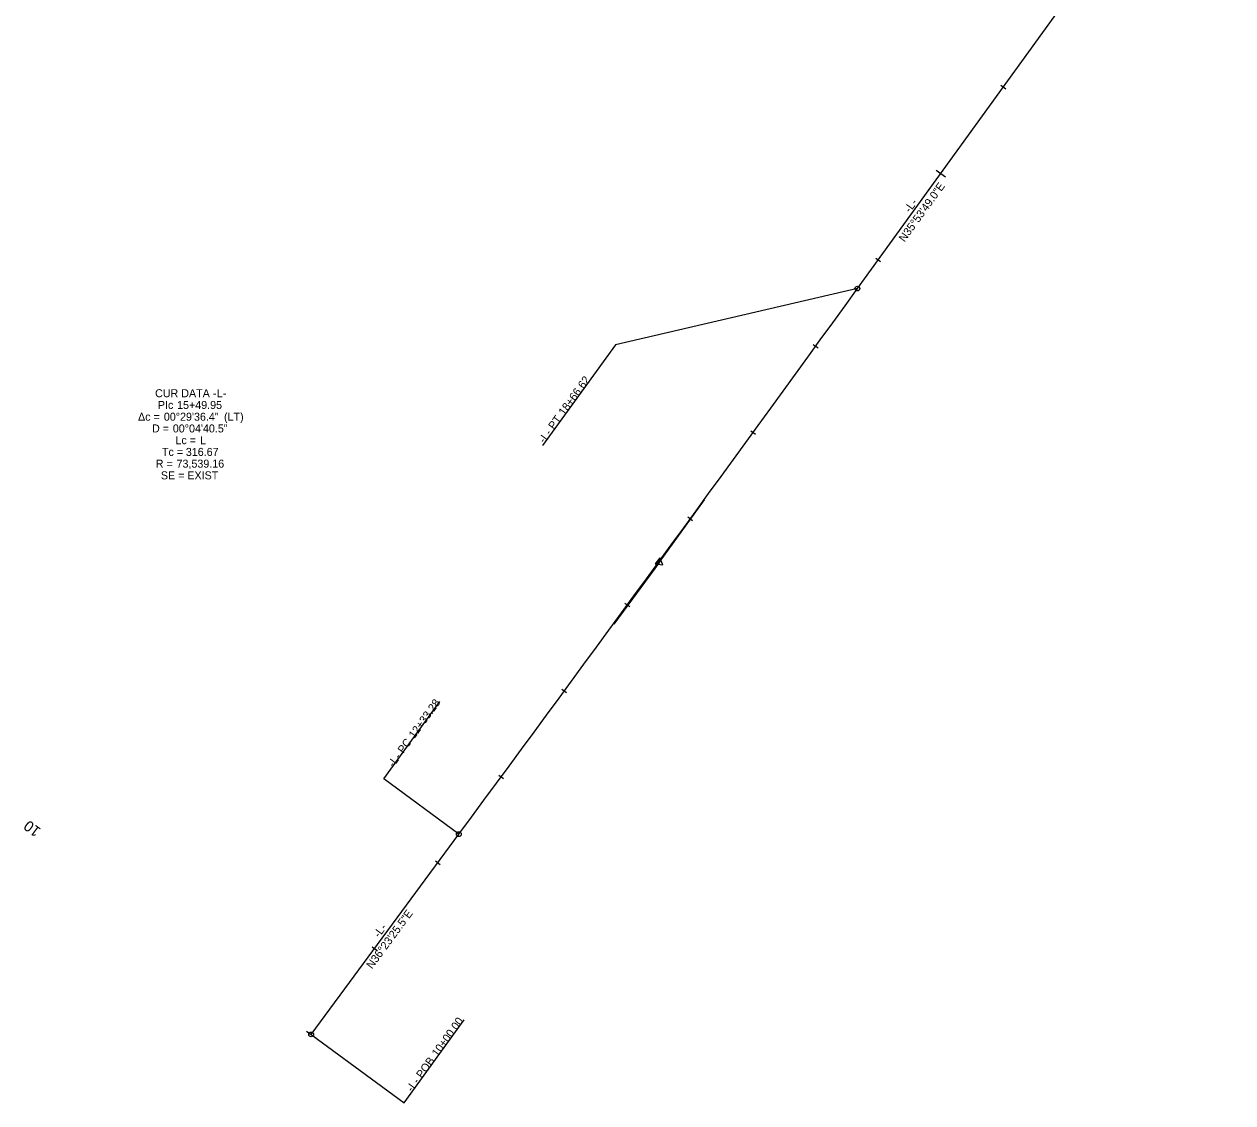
# Model space of a CAD drawing. Extents: x 1183553 to 1185476, y 573018 to 575071.
# Drawn here: x 1183553 to 1184686, y 573018 to 574030 of the extents above; entities that cross this region are included whole.
import ezdxf

# ---------------------------------------------------------------- set-up
doc = ezdxf.new("R2010")
doc.units = 0
for name, color, linetype in [('CTL Secondary Horizontal and Vertical Cogo Number', 7, 'Continuous'), ('Default', 7, 'Continuous'), ('Exist Utilities Telephone Hand Hole CELL', 7, 'Continuous'), ('Exist Utilities Telephone Hand Hole Cogo Elevation', 7, 'Continuous'), ('Exist Utilities Telephone Hand Hole Cogo Number', 7, 'Continuous'), ('Exist Utilities Telephone UG Conduit SUE LOS B Cogo Comment', 7, 'Continuous'), ('Exist Utilities Telephone UG Conduit SUE LOS B Cogo Elevation', 7, 'Continuous'), ('Exist Utilities Telephone UG Conduit SUE LOS B Cogo Number', 7, 'Continuous')]:
    doc.layers.add(name, color=color, linetype=linetype)

msp = doc.modelspace()

# ---------------------------------------------------------------- linework, layer by layer
at = {"layer": 'CTL Secondary Horizontal and Vertical Cogo Number'}
for p, q in [((1184334.3, 573781.9), (1184686.2, 574268)), ((1183822.4, 573082.6), (1183960.8, 573270.4))]:
    msp.add_line(p, q, dxfattribs=at)
msp.add_arc((1124762.3, 616900), 73539.2, 323.609593, 324.103043, dxfattribs=at)
at = {"layer": 'Default'}
for p, q in [((1184334.3, 573781.9), (1184686.2, 574268)), ((1184148.7, 573525.3), (1184190.9, 573583.7)), ((1184148.7, 573525.3), (1184106, 573467.4)), ((1184148.7, 573525.3), (1184148.7, 573525.3)), ((1183822.4, 573082.6), (1183960.8, 573270.4))]:
    msp.add_line(p, q, dxfattribs=at)
msp.add_lwpolyline([(1184152, 573522.9), (1184149.1, 573529.5), (1184144.9, 573523.7)], close=True, dxfattribs=at)
msp.add_arc((1124762.3, 616900), 73539.2, 323.609593, 324.103043, dxfattribs=at)
at = {"layer": 'Exist Utilities Telephone Hand Hole CELL'}
for p, q in [((1184334.3, 573781.9), (1184107.6, 573729.3)), ((1184107.6, 573729.3), (1184039.2, 573634.8)), ((1183890.6, 573322.1), (1183943.1, 573394.6)), ((1183960.8, 573270.4), (1183890.6, 573322.1)), ((1183909.4, 573018.5), (1183965.7, 573096.3)), ((1183822.4, 573082.6), (1183909.4, 573018.5))]:
    msp.add_line(p, q, dxfattribs=at)
for centre in [(1184334.3, 573781.9), (1183960.8, 573270.4), (1183822.4, 573082.6)]:
    msp.add_circle(centre, 2.25, dxfattribs=at)
at = {"layer": 'Exist Utilities Telephone UG Conduit SUE LOS B Cogo Elevation'}
for p, q in [((1184408.2, 573893), (1184416.8, 573886.8)), ((1183818.1, 573085.8), (1183826.6, 573079.5))]:
    msp.add_line(p, q, dxfattribs=at)
at = {"layer": 'Exist Utilities Telephone UG Conduit SUE LOS B Cogo Number'}
for p, q in [((1184468.9, 573972.5), (1184473.4, 573969.3)), ((1184351.7, 573810.5), (1184356.1, 573807.3)), ((1184293, 573729.5), (1184297.5, 573726.3)), ((1184234.3, 573648.6), (1184238.7, 573645.4)), ((1184175.4, 573567.8), (1184179.9, 573564.5)), ((1184116.4, 573487), (1184120.9, 573483.8)), ((1184057.3, 573406.4), (1184061.8, 573403.1)), ((1183998.1, 573325.8), (1184002.6, 573322.5)), ((1183938.8, 573245.3), (1183943.3, 573242)), ((1183879.5, 573164.8), (1183883.9, 573161.5))]:
    msp.add_line(p, q, dxfattribs=at)

# ---------------------------------------------------------------- texts
at = {"layer": 'Exist Utilities Telephone Hand Hole CELL'}
for s, p in [('18+66.62', (1184059.6, 573662.3)), ('PT', (1184050, 573649.1)), ('L', (1184042.9, 573639.2)), ('- ', (1184046.3, 573643.9)), ('-', (1184040.8, 573636.4)), ('12+33.28', (1183919.1, 573359.5)), ('PC', (1183908.8, 573345.4)), ('L', (1183901.6, 573335.5)), ('-', (1183899.6, 573332.6)), ('- ', (1183905.1, 573340.2)), ('10+00.00', (1183940.8, 573061.1)), ('POB', (1183926.2, 573040.9)), ('L', (1183919, 573031)), ('-', (1183917, 573028.1)), ('- ', (1183922.4, 573035.7))]:
    msp.add_text(s, height=7.5, rotation=54.103, dxfattribs=at).set_placement(p)
at = {"layer": 'Exist Utilities Telephone Hand Hole Cogo Elevation'}
for s, p in [('CUR DATA -', (1183676.1, 573680)), ('L', (1183733.9, 573680)), ('PIc ', (1183678.7, 573669)), ('15+49.95', (1183696.7, 573669)), ('-', (1183739.7, 573680)), ('Δc = ', (1183660.1, 573658)), ('00°29\'36.4"', (1183684.3, 573658)), (' (LT)', (1183737.9, 573658)), ('D = ', (1183673.2, 573647)), ('00°04\'40.5"', (1183692.7, 573647)), ('Lc = ', (1183695.2, 573636)), ('L', (1183718.2, 573636)), ('Tc = ', (1183682.5, 573625)), ('316.67', (1183704.9, 573625)), ('R = ', (1183676.7, 573614)), ('73,539.16', (1183696.2, 573614)), ('SE = EXIST', (1183681.5, 573603))]:
    msp.add_text(s, height=7.5, dxfattribs=at).set_placement(p)
at = {"layer": 'Exist Utilities Telephone Hand Hole Cogo Number'}
for s, rotation, p in [('N35°53\'49.0"E', 54.103, (1184378.5, 573825)), ('L', 54.103, (1184385.6, 573855.3)), ('-', 54.103, (1184389, 573860)), ('-', 54.103, (1184383.6, 573852.4)), ('N36°23\'25.5"E', 53.6096, (1183879.4, 573143.5)), ('L', 53.6096, (1183888.1, 573175.6)), ('-', 53.6096, (1183891.6, 573180.3)), ('-', 53.6096, (1183886.1, 573172.8))]:
    msp.add_text(s, height=7.5, rotation=rotation, dxfattribs=at).set_placement(p)
at = {"layer": 'Exist Utilities Telephone UG Conduit SUE LOS B Cogo Comment'}
msp.add_text('10', height=10, rotation=143.6096, dxfattribs=at).set_placement((1183569.7, 573275.1))

doc.saveas('drawing.dxf')
